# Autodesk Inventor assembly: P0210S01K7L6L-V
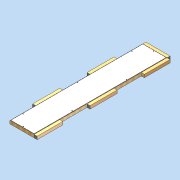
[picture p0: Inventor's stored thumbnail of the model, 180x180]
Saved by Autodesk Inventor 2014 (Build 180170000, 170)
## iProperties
Created: 2011-04
Part Number: P0210S01K7L6L-V
Document SubType Name: Assembly
Designer: david.appleford
Mass: 36000 g
Surface Area: 48094.5 cm^2
Volume: 144709 cm^3
Density: 0.248775 g/cm^3
Description: 0.5w x 2.5w 01 Panel - 7 Locks 6 Lugs LH
Cost Center: £141.00
Justset: False
Author: david.appleford
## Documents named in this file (5)
- C:\Documents and Settings\john.everitt\Local Settings\My Documents\Vault\Production MkII\VIRTUAL ELEMENTS\Virtual Walls\Virtual Timber + MgO\P0210S01K7L6L-V.iam
- C:\Documents and Settings\john.everitt\Local Settings\My Documents\Vault\Production MkII\VIRTUAL ELEMENTS\Virtual Lugs\Superceded Lugs\LA02C3V.ipt
- C:\Documents and Settings\john.everitt\Local Settings\My Documents\Vault\Production MkII\VIRTUAL ELEMENTS\Virtual Lugs\Superceded Lugs\LA02M3V.ipt
- C:\Documents and Settings\john.everitt\Local Settings\My Documents\Vault\Production MkII\VIRTUAL ELEMENTS\Virtual Walls\Virtual Timber + MgO\P0210S01K7-V.ipt
- C:\Documents and Settings\john.everitt\Local Settings\My Documents\Vault\Production MkII\VIRTUAL ELEMENTS\Virtual Lugs\Superceded Lugs\LA02E3V.ipt
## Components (7 placed, 4 different names)
1. P0210S01K7-V:1 — Mate:1, Flush:1, Flush:2, Mate:5, Mate:6, Flush:9, Flush:10, Mate:7, Mate:8, Flush:11, Flush:12, Flush:13, Flush:14, Mate:14
2. LA02C3V:1 — Mate:1, Flush:1, Flush:2, Mate:9, Mate:13
3. LA02M3V:1 — Mate:6, Flush:9, Mate:12
4. LA02M3V:2 — Mate:5, Flush:10, Mate:12, Mate:13
5. LA02C3V:4 — Mate:8, Flush:12, Mate:10
6. LA02M3V:4 — Mate:7, Flush:11, Mate:9, Mate:10
7. LA02E3V:1 — Flush:13, Flush:14, Mate:14
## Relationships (18: Mate 10, Flush 8)
- Mate:1: P0210S01K7-V:1 ↔ LA02C3V:1
- Flush:1: P0210S01K7-V:1 ↔ LA02C3V:1
- Flush:2: P0210S01K7-V:1 ↔ LA02C3V:1
- Mate:5: P0210S01K7-V:1 ↔ LA02M3V:2
- Mate:6: P0210S01K7-V:1 ↔ LA02M3V:1
- Flush:9: P0210S01K7-V:1 ↔ LA02M3V:1
- Flush:10: P0210S01K7-V:1 ↔ LA02M3V:2
- Mate:7: P0210S01K7-V:1 ↔ LA02M3V:4
- Mate:8: P0210S01K7-V:1 ↔ LA02C3V:4
- Flush:11: P0210S01K7-V:1 ↔ LA02M3V:4
- Flush:12: P0210S01K7-V:1 ↔ LA02C3V:4
- Mate:9: LA02C3V:1 ↔ LA02M3V:4
- Mate:10: LA02C3V:4 ↔ LA02M3V:4
- Mate:12: LA02M3V:1 ↔ LA02M3V:2
- Mate:13: LA02C3V:1 ↔ LA02M3V:2
- Flush:13: P0210S01K7-V:1 ↔ LA02E3V:1
- Flush:14: P0210S01K7-V:1 ↔ LA02E3V:1
- Mate:14: P0210S01K7-V:1 ↔ LA02E3V:1
## Named parameters: t = 1 mm, Cl = 2 mm
